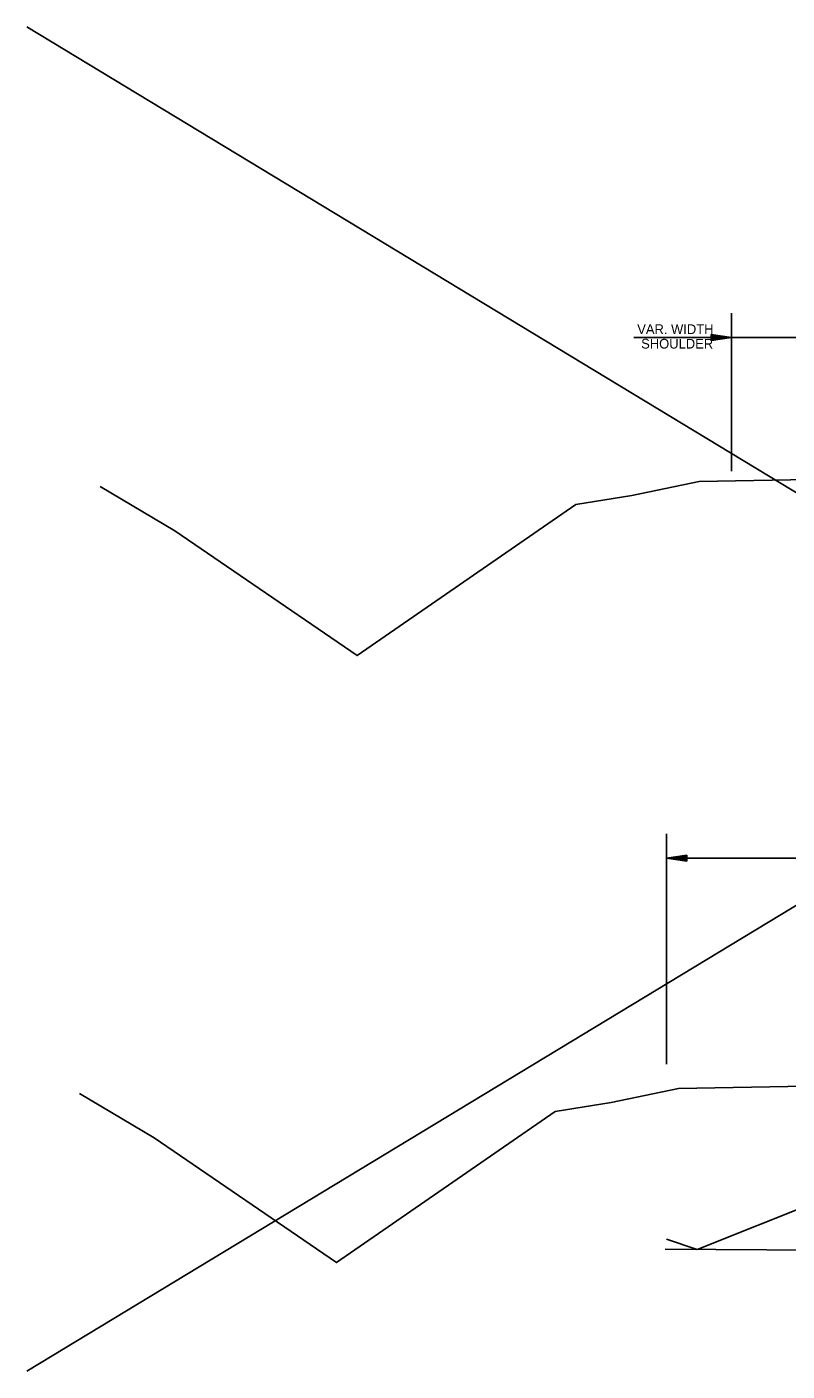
# Model space of a CAD drawing. Extents: x 1807779 to 1818251, y 673292 to 678849.
# Drawn here: x 1814426 to 1814991, y 673292 to 674291 of the extents above; entities that cross this region are included whole.
import ezdxf

# ---------------------------------------------------------------- set-up
doc = ezdxf.new("R2010")
doc.units = 0
for name, color, linetype in [('Default', 7, 'Continuous'), ('Dimensions', 7, 'Continuous'), ('S_PHOTO_CTL_ANNOT', 7, 'Continuous'), ('T_Drafting', 7, 'Continuous')]:
    doc.layers.add(name, color=color, linetype=linetype)

msp = doc.modelspace()

# ---------------------------------------------------------------- linework, layer by layer
at = {"layer": 'Default'}
for p, q in [((1815180.06, 673485.16), (1814924.01, 673382.79)), ((1814901.24, 673390.38), (1814924.01, 673382.79)), ((1815366.21, 673379.4), (1814900.26, 673382.97))]:
    msp.add_line(p, q, dxfattribs=at)
at = {"layer": 'Dimensions'}
for p, q in [((1814949.35, 673961.14), (1814949.35, 674078.61)), ((1814876.97, 674060.57), (1815105.79, 674060.57)), ((1814934.35, 674062.82), (1814949.35, 674060.57)), ((1814934.35, 674062.82), (1814934.35, 674058.32)), ((1814934.35, 674062.44), (1814946.85, 674060.57)), ((1814934.35, 674062.06), (1814944.27, 674060.57)), ((1814934.35, 674061.69), (1814941.77, 674060.57)), ((1814934.35, 674061.3), (1814939.23, 674060.57)), ((1814934.35, 674060.92), (1814936.72, 674060.57)), ((1814934.35, 674058.32), (1814949.35, 674060.57)), ((1814934.35, 674059.83), (1814939.23, 674060.57)), ((1814934.35, 674059.08), (1814944.27, 674060.57)), ((1814934.35, 674058.69), (1814946.85, 674060.57)), ((1814934.35, 674059.45), (1814941.77, 674060.57)), ((1814934.35, 674060.22), (1814936.72, 674060.57)), ((1814901.24, 673520.56), (1814901.24, 673691.59)), ((1814916.24, 673675.79), (1814901.24, 673673.54)), ((1814916.24, 673675.42), (1814903.74, 673673.54)), ((1814916.24, 673675.03), (1814906.32, 673673.54)), ((1814916.24, 673674.66), (1814908.82, 673673.54)), ((1814916.24, 673671.29), (1814916.24, 673675.79)), ((1814901.24, 673673.54), (1815403.54, 673673.54)), ((1814916.24, 673671.29), (1814901.24, 673673.54)), ((1814916.24, 673671.67), (1814903.74, 673673.54)), ((1814916.24, 673672.05), (1814906.32, 673673.54)), ((1814916.24, 673672.42), (1814908.82, 673673.54)), ((1814916.24, 673674.28), (1814911.36, 673673.54)), ((1814916.24, 673672.81), (1814911.36, 673673.54)), ((1814916.24, 673673.89), (1814913.87, 673673.54)), ((1814916.24, 673673.19), (1814913.87, 673673.54))]:
    msp.add_line(p, q, dxfattribs=at)
at = {"layer": 'S_PHOTO_CTL_ANNOT'}
for p, q in [((1814425.79, 674291.38), (1816075.79, 673292.32)), ((1814425.79, 673292.32), (1816075.79, 674291.38))]:
    msp.add_line(p, q, dxfattribs=at)
at = {"layer": 'T_Drafting'}
for points in [[(1814480.16, 673949.87), (1814535.82, 673916.91), (1814671.2, 673824.11), (1814833.77, 673936.36), (1814875.27, 673943.12), (1814925.5, 673953.52), (1815020.37, 673955.18), (1815100.55, 673956.25), (1815260.54, 673954.11), (1815289.01, 673953.47), (1815317.34, 673949.88), (1815367.9, 673935.45), (1815415.36, 673922.36), (1815530.07, 673861.35), (1815607.52, 673843.51), (1815663.01, 673838.86), (1815719.46, 673834.02), (1815906.27, 673833.05), (1815973.94, 673835.62)], [(1814464.84, 673498.76), (1814520.5, 673465.8), (1814655.88, 673373), (1814818.45, 673485.25), (1814859.95, 673492.01), (1814910.18, 673502.42), (1815005.05, 673504.07), (1815085.23, 673505.14), (1815245.22, 673503), (1815273.69, 673502.36), (1815302.02, 673498.78), (1815352.58, 673484.34), (1815400.04, 673471.25), (1815514.75, 673410.24), (1815592.2, 673392.41), (1815647.69, 673387.75), (1815704.14, 673382.92), (1815890.95, 673381.94), (1815958.62, 673384.51)]]:
    msp.add_lwpolyline(points, dxfattribs=at)

# ---------------------------------------------------------------- texts
at = {"layer": 'Dimensions'}
for s, p in [('VAR. WIDTH', (1814879.4, 674063.12)), ('SHOULDER', (1814882.31, 674052.32))]:
    msp.add_text(s, height=7.2, dxfattribs=at).set_placement(p)

doc.saveas('drawing.dxf')
